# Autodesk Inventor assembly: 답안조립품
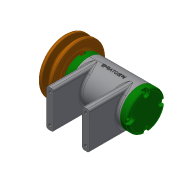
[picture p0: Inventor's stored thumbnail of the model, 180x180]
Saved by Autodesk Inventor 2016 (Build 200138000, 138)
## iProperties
Created: 2020-07
Part Number: 답안조립품
Document SubType Name: Assembly
Designer: user
Author: user
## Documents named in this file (11)
- C:\Users\user\Desktop\700706V1005\답안조립품.iam
- C:\Users\user\Desktop\700706V1005\본체.ipt
- C:\Users\user\Desktop\700706V1005\베어링 6002.ipt
- C:\Users\user\Desktop\700706V1005\앞커버.ipt
- C:\Users\user\Desktop\700706V1005\뒤커버.ipt
- C:\Users\user\Desktop\700706V1005\축.ipt
- C:\Users\user\Desktop\700706V1005\오일 실 15 25 7.ipt
- C:\Users\user\Desktop\700706V1005\Ű 3x3x12.ipt
- C:\Users\user\Desktop\700706V1005\V벨트풀리.ipt
- C:\Users\user\Desktop\700706V1005\와셔 8x17.ipt
- C:\Users\user\Desktop\700706V1005\스프링와셔 8.ipt
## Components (2 placed, 2 different names)
1. Ű 3x3x12:1
2. V벨트풀리:1
